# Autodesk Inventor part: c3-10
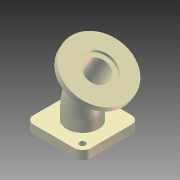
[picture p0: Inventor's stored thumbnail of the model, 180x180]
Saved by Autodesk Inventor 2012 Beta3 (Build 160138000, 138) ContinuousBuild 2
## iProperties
Created: 2010-11
Part Number: c3-10
Material: Cast Iron
Document SubType Name: Modeling
Designer: Beta-8540w
Density: 7.25 g/cm^3
Mass: 1087.5 g
Surface Area: 260 cm^2
Volume: 150 cm^3
Author: Beta-8540w
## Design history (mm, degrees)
sketch "Sketch1"
  geometry: L1 (-50, -50)-(50, -50); L2 (50, -50)-(50, 50); L3 (50, 50)-(-50, 50); L4 (-50, 50)-(-50, -50); C1 r 20 at (0, 0); C2 r 28 at (0, 0); 3 further points
  constraints: 8 end point, 3 perpendicular, 2 centre point, 2 coincident, 2 midpoint, 1 horizontal, 1 horizontal alignment, 1 parallel, 1 vertical alignment
  dimensions: "Width" = 100 distance of L1.start L1.end; "d6" = 40 diameter of C1; "d7" = 8 radial gap between concentric circles of C2 C1
extrude "Extrusion1" new body sketch "Sketch1" distance "d3" = 15; taper "d4" = 0 deg
fillet "Fillet1" dims "d5" = 14
sketch "Sketch2"
  geometry: L1 (0, 0)-(0, 30); L2 (-13.397, 80)-(-28.397, 105.981); A1 r 100 centre (-100, 30) between (0, 30) and (-13.397, 80)
  constraints: 4 end point, 2 point on circle, 2 tangent, 1 centre point, 1 vertical
  dimensions: "d8" = 30 distance of L1.start L1.end; "d9" = 100 radius of A1; "d10" = 30 distance of L2.start L2.end; "d11" = 30 deg angle of L2 L1
sketch "Sketch3"
  geometry: L1 (-13.397, 80)-(-28.397, 105.981) reference; L2 (-28.397, 105.981)-(-76.029, 78.481); L3 (-76.029, 78.481)-(-71.029, 69.821); L4 (-71.029, 69.821)-(-23.397, 97.321); L5 (-23.397, 97.321)-(-28.397, 105.981); 1 further point
  constraints: 8 end point, 2 parallel, 2 perpendicular
  dimensions: "d16" = 10 distance of L3.end L2.end; "d17" = 110 diameter of L3 L5
revolve "Revolution1" sketch "Sketch3" stored, may be unused: angle "d18" = 90 deg
sweep "Sweep1" dims "d19" = 0
sweep "Sweep2" dims "d20" = 0
sketch "Sketch4"
  geometry: C1 r 20 at (0, 0) reference; C2 r 55 at (0, 0) reference; C3 r 27.5 at (0, 0); 1 further point
  constraints: 1 centre point, 1 coincident
  dimensions: "d21" = 55 diameter of C3
extrude "Extrusion2" cut sketch "Sketch4" distance "d22" = 5; taper "d23" = 0 deg
sketch "Sketch5"
  geometry: L1 (0, 0)-(0, 9.711); L2 (-25, 0)-(-27, 0); L3 (-27, 0)-(-27, 1.5); L4 (-26.5, 2)-(-25.5, 2); L5 (-25, 1.5)-(-25, 0); A1 r 0.5 centre (-25.5, 1.5) between (-25, 1.5) and (-25.5, 2); A2 r 0.5 centre (-26.5, 1.5) between (-26.5, 2) and (-27, 1.5); 1 further point
  constraints: 10 end point, 4 point on circle, 4 tangent, 3 point on line, 2 centre point, 2 parallel, 1 equal radius, 1 horizontal, 1 perpendicular, 1 vertical
  dimensions: "d24" = 2 distance of L2.start L2.end; "d25" = 2 distance of point (-25, 2) L2.start; "d26" = 50 diameter of L5 L1; "d27" = 0.5 radius of A1
revolve "Revolution2" sketch "Sketch5" stored, may be unused: angle "d28" = 90 deg
hole "Hole1" diameter "d31" = 11; stored, may be unused: countersink angle "d35" = 7.5 deg, drill point angle "d37" = 118 deg; dims "d29" = 10, "d30" = 10, "d32" = 6, "d33" = 28, "d34" = 2, "d36" = 8
body "Solid1"
